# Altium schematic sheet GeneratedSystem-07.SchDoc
size 101 x 76 mm
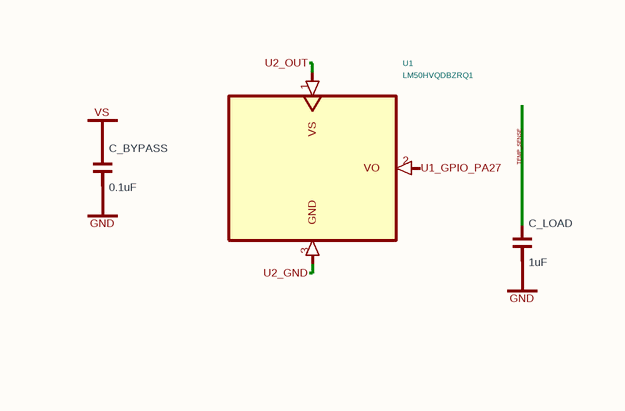
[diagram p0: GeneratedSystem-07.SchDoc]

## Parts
C_BYPASS  0.1uF
C_LOAD  1uF
U1  (no value)

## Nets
GND: C_BYPASS.2(cathode) C_LOAD.2(cathode)
VS: C_BYPASS.1(anode)
U1_GPIO_PA27: U1.2(VO)
U2_GND: U1.3(GND)
U2_OUT: U1.1(VS)

Not connected (* = marked no-connect by the designer): C_LOAD 1(anode)

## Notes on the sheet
- TEMP_SENSE

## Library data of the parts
C_BYPASS C_LOAD = capacitor_down
U1 = U1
